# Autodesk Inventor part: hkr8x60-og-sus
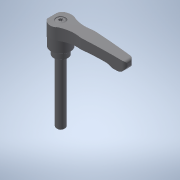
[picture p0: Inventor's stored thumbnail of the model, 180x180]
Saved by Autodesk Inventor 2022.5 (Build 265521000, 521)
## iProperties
Created: 2017-09
Part Number: hkr8x60-og-sus
Material: 一般
Document SubType Name: Modeling
Designer: imaocorp
Density: 1 g/cm^3
Appearance: 既定
Author: imaocorp
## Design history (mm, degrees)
node "hkr8x60-og-sus.x_t1"
node "hkr8x60-og-sus"
node "Base1"
